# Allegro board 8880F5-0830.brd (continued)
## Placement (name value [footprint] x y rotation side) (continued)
NOREF#872  -  []  119.95 195.15 0 top
NOREF#873  -  []  320.83 194.63 0 top
NOREF#874  -  []  392.24 199.18 90 top
NOREF#875  -  []  215.96 248.49 0 top
NOREF#876  -  []  406.19 188.15 0 top
NOREF#877  -  []  392.47 288.57 90 top
NOREF#878  -  []  262.04 224.74 0 top
NOREF#879  -  []  374.88 217.11 0 top
NOREF#880  -  []  329.16 296.86 0 top
NOREF#881  -  []  406.94 131.34 90 top
NOREF#882  -  []  465.81 179.15 0 top
NOREF#883  -  []  400.79 154.88 0 top
NOREF#884  -  []  390.53 171.64 0 top
NOREF#885  -  []  223.15 211.32 90 top
NOREF#886  -  []  417.7 154.88 0 top
NOREF#887  -  []  387.08 154.88 0 top
NOREF#888  -  []  419.9 240.56 90 top
NOREF#889  -  []  201.66 213.45 90 top
NOREF#890  -  []  352.24 243.59 90 top
NOREF#891  -  []  406.95 131.44 90 top
NOREF#892  -  []  272.55 243.91 0 top
NOREF#893  -  []  381.2 226.12 90 top
NOREF#894  -  []  409.49 180.15 0 top
NOREF#895  -  []  200.98 260.9 90 top
NOREF#896  -  []  272.66 288.86 90 top
NOREF#897  -  []  201.23 233.47 90 top
NOREF#898  -  []  168.13 172.56 90 top
NOREF#899  -  []  251.06 225.04 90 top
NOREF#900  -  []  419.73 131.89 90 top
NOREF#901  -  []  467.51 186.77 0 top
NOREF#902  -  []  460.93 191.31 90 top
NOREF#903  -  []  192.47 205.19 90 top
NOREF#904  -  []  419.9 272.82 90 top
NOREF#905  -  []  409.17 249.11 0 top
NOREF#906  -  []  184.47 241.43 0 top
NOREF#907  -  []  303.47 154.05 0 top
NOREF#908  -  []  340.61 286.96 90 top
NOREF#909  -  []  175.7 177.76 90 top
NOREF#910  -  []  272.55 245.18 0 top
NOREF#911  -  []  216.96 240.71 0 top
NOREF#912  -  []  295.96 248.49 0 top
NOREF#913  -  []  418.63 131.94 90 top
NOREF#914  -  []  115.61 211.51 90 top
NOREF#915  -  []  199.33 240.28 90 top
NOREF#916  -  []  117.26 190.55 90 top
NOREF#917  -  []  252.51 265.56 0 top
NOREF#918  -  []  327.27 131.64 90 top
NOREF#919  -  []  192.47 177.76 90 top
NOREF#920  -  []  122.15 195.15 0 top
NOREF#921  -  []  311.44 288.86 0 top
NOREF#922  -  []  351.34 183.91 0 top
NOREF#923  -  []  317.57 269.63 90 top
NOREF#924  -  []  390.94 224.9 90 top
NOREF#925  -  []  209.23 236.67 90 top
NOREF#926  -  []  398.65 289.12 0 top
NOREF#927  -  []  331.06 163.82 90 top
NOREF#928  -  []  108.01 195.15 0 top
NOREF#929  -  []  369.38 241.11 0 top
NOREF#930  -  []  351.04 241.69 0 top
NOREF#931  -  []  177.33 228.47 90 top
NOREF#932  -  []  352.55 182.64 0 top
NOREF#933  -  []  310.43 243.09 0 top
NOREF#934  -  []  230.73 193.69 0 top
NOREF#935  -  []  122.15 222.33 0 top
NOREF#936  -  []  194.09 228.47 90 top
NOREF#937  -  []  251.54 252.73 90 top
NOREF#938  -  []  306.27 216.63 90 top
NOREF#939  -  []  343.31 224.74 0 top
NOREF#940  -  []  451.68 171.53 0 top
NOREF#941  -  []  258.2 186.67 0 top
NOREF#942  -  []  175.7 209.49 90 top
NOREF#943  -  []  377.23 257.16 90 top
NOREF#944  -  []  392.47 272.56 90 top
NOREF#945  -  []  298.16 237.06 0 top
NOREF#946  -  []  262.04 164.74 0 top
NOREF#947  -  []  346.08 288.86 0 top
NOREF#948  -  []  287.91 280.1 0 top
NOREF#949  -  []  110.47 178.64 0 top
NOREF#950  -  []  201.49 151.93 90 top
NOREF#951  -  []  271.34 245.18 0 top
NOREF#952  -  []  354.37 130.67 90 top
NOREF#953  -  []  313.94 286.96 90 top
NOREF#954  -  []  175.8 133.97 90 top
NOREF#955  -  []  304.82 146.05 0 top
NOREF#956  -  []  332.51 265.55 0 top
NOREF#957  -  []  166.06 175.58 90 top
NOREF#958  -  []  309.51 183.41 0 top
NOREF#959  -  []  343.83 231.63 90 top
NOREF#960  -  []  184.47 201.89 90 top
NOREF#961  -  []  230.73 253.69 0 top
NOREF#962  -  []  406.65 271.21 90 top
NOREF#963  -  []  477.24 239.09 0 top
NOREF#964  -  []  331.94 264.65 90 top
NOREF#965  -  []  342.04 224.72 0 top
NOREF#966  -  []  306.92 146.05 0 top
NOREF#967  -  []  115.99 130.36 90 top
NOREF#968  -  []  401.52 210.88 90 top
NOREF#969  -  []  385.61 208.66 90 top
NOREF#970  -  []  383.07 180.2 90 top
NOREF#971  -  []  257.09 224.74 90 top
NOREF#972  -  []  327.57 205.86 90 top
NOREF#973  -  []  303.15 271.32 90 top
NOREF#974  -  []  168.69 290.01 90 top
NOREF#975  -  []  106.36 190.55 0 top
NOREF#976  -  []  465.81 222.58 0 top
NOREF#977  -  []  337.09 223.52 90 top
NOREF#978  -  []  331.62 204.35 90 top
NOREF#979  -  []  456.08 230.2 0 top
NOREF#980  -  []  310.43 183.09 0 top
NOREF#981  -  []  261.63 233.83 90 top
NOREF#982  -  []  339.33 204.35 90 top
NOREF#983  -  []  175.8 174.36 90 top
NOREF#984  -  []  247.89 264.35 90 top
NOREF#985  -  []  263.71 288.86 0 top
NOREF#986  -  []  383.07 163.44 90 top
NOREF#987  -  []  387.39 281.11 0 top
NOREF#988  -  []  201.66 240.88 90 top
NOREF#989  -  []  418.37 273.42 90 top
NOREF#990  -  []  175.8 256.4 90 top
NOREF#991  -  []  451.68 214.96 0 top
NOREF#992  -  []  352.24 184.86 90 top
NOREF#993  -  []  342.36 225.04 90 top
NOREF#994  -  []  394.66 274.38 90 top
NOREF#995  -  []  346.27 132.97 90 top
NOREF#996  -  []  251.54 192.73 90 top
NOREF#997  -  []  317.05 288.86 0 top
NOREF#998  -  []  201.66 186.02 90 top
NOREF#999  -  []  346.27 129.42 90 top
NOREF#1000  -  []  380.59 287.22 0 top
NOREF#1001  -  []  266.49 143.19 0 top
NOREF#1002  -  []  118.96 179.19 0 top
NOREF#1003  -  []  306.85 271.67 0 top
NOREF#1004  -  []  199.33 185.42 90 top
NOREF#1005  -  []  319.33 176.03 90 top
NOREF#1006  -  []  234.7 298.51 0 top
NOREF#1007  -  []  167.7 132.72 90 top
NOREF#1008  -  []  456.08 186.77 0 top
NOREF#1009  -  []  371.48 257.11 0 top
NOREF#1010  -  []  110.21 222.33 0 top
NOREF#1011  -  []  230.43 248.88 0 top
NOREF#1012  -  []  167.7 192.32 90 top
NOREF#1013  -  []  404.15 289.12 0 top
NOREF#1014  -  []  423.61 188.92 90 top
NOREF#1015  -  []  392.04 241.11 90 top
NOREF#1016  -  []  167.7 242.78 90 top
NOREF#1017  -  []  273.09 288.41 90 top
NOREF#1018  -  []  165.8 171.96 90 top
NOREF#1019  -  []  310.43 188.88 90 top
NOREF#1020  -  []  397.8 179.7 90 top
NOREF#1021  -  []  259.33 205.55 0 top
NOREF#1022  -  []  330.49 224.74 90 top
NOREF#1023  -  []  425.2 161.74 90 top
NOREF#1024  -  []  229.21 247.61 0 top
NOREF#1025  -  []  481.96 273.87 90 top
NOREF#1026  -  []  249.6 163.52 90 top
NOREF#1027  -  []  229.51 253.69 0 top
NOREF#1028  -  []  392.73 188.15 0 top
NOREF#1029  -  []  239.33 183.63 90 top
NOREF#1030  -  []  473.79 239.64 0 top
NOREF#1031  -  []  462.06 274.77 90 top
NOREF#1032  -  []  336.45 164.74 0 top
NOREF#1033  -  []  184.47 214 0 top
NOREF#1034  -  []  463.11 186.77 0 top
NOREF#1035  -  []  396.55 257.37 0 top
NOREF#1036  -  []  257.9 186.99 0 top
NOREF#1037  -  []  127.81 175.44 90 top
NOREF#1038  -  []  230.73 249.2 0 top
NOREF#1039  -  []  201.21 276.04 90 top
NOREF#1040  -  []  331.38 163.52 90 top
NOREF#1041  -  []  475.04 195.66 0 top
NOREF#1042  -  []  478.57 259.9 90 top
NOREF#1043  -  []  251.62 205.56 90 top
NOREF#1044  -  []  284.77 146.93 90 top
NOREF#1045  -  []  184.47 192.32 90 top
NOREF#1046  -  []  229.51 246.66 0 top
NOREF#1047  -  []  309.51 246.66 0 top
NOREF#1048  -  []  119.95 187.53 0 top
NOREF#1049  -  []  392.24 193.43 90 top
NOREF#1050  -  []  334.29 204.35 90 top
NOREF#1051  -  []  332.51 204.35 90 top
NOREF#1052  -  []  252.83 265.86 90 top
NOREF#1053  -  []  386.53 148.15 90 top
NOREF#1054  -  []  415.6 146.88 0 top
NOREF#1055  -  []  124.1 231.22 0 top
NOREF#1056  -  []  413.75 171.64 0 top
NOREF#1057  -  []  329.28 165.04 90 top
NOREF#1058  -  []  424.05 163.64 90 top
NOREF#1059  -  []  371.73 289.12 0 top
NOREF#1060  -  []  475.04 195.66 0 top
NOREF#1061  -  []  120.24 171.1 0 top
NOREF#1062  -  []  383.09 273.11 0 top
NOREF#1063  -  []  295.19 271.65 90 top
NOREF#1064  -  []  331.62 205.56 0 top
NOREF#1065  -  []  108.01 214.71 0 top
NOREF#1066  -  []  310.83 224.63 0 top
NOREF#1067  -  []  184.47 165.4 90 top
NOREF#1068  -  []  419.47 273.37 90 top
NOREF#1069  -  []  396.55 257.37 0 top
NOREF#1070  -  []  334.61 205.86 90 top
NOREF#1071  -  []  384.17 180.15 90 top
NOREF#1072  -  []  309.21 183.09 0 top
NOREF#1073  -  []  118.7 222.88 0 top
NOREF#1074  -  []  340.83 174.63 90 top
NOREF#1075  -  []  388.43 146.88 0 top
NOREF#1076  -  []  450.03 234.74 0 top
NOREF#1077  -  []  398.65 209.36 90 top
NOREF#1078  -  []  166.06 189.04 90 top
NOREF#1079  -  []  258.35 288.91 90 top
NOREF#1080  -  []  217.41 213.24 90 top
NOREF#1081  -  []  230.43 187.61 0 top
NOREF#1082  -  []  341.63 173.83 90 top
NOREF#1083  -  []  390.53 180.15 0 top
NOREF#1084  -  []  373.87 188.15 0 top
NOREF#1085  -  []  395.2 297.12 0 top
NOREF#1086  -  []  310.41 187.61 90 top
NOREF#1087  -  []  330.17 225.04 90 top
NOREF#1088  -  []  223.56 245.29 90 top
NOREF#1089  -  []  272.25 181.05 90 top
NOREF#1090  -  []  396.55 273.11 0 top
NOREF#1091  -  []  473.79 196.21 0 top
NOREF#1092  -  []  326.23 173.13 0 top
NOREF#1093  -  []  400.24 195.88 90 top
NOREF#1094  -  []  327.57 204.65 90 top
NOREF#1095  -  []  35.83 128.17 90 top
NOREF#1096  -  []  124.61 178.64 0 top
NOREF#1097  -  []  184.47 204.09 90 top
NOREF#1098  -  []  201.49 161 90 top
NOREF#1099  -  []  408.63 290.39 90 top
NOREF#1100  -  []  184.47 260.9 90 top
NOREF#1101  -  []  318.45 197.01 0 top
NOREF#1102  -  []  461.86 230.75 0 top
NOREF#1103  -  []  184.47 149.48 90 top
NOREF#1104  -  []  167.7 233.47 90 top
NOREF#1105  -  []  400.85 297.12 0 top
NOREF#1106  -  []  175.7 246.08 90 top
NOREF#1107  -  []  115.36 235.64 90 top
NOREF#1108  -  []  381.2 290.39 90 top
NOREF#1109  -  []  456.04 179.06 0 top
NOREF#1110  -  []  165.8 212.85 90 top
NOREF#1111  -  []  201.23 247.18 90 top
NOREF#1112  -  []  167.7 255.15 0 top
NOREF#1113  -  []  528.1 276.41 90 top
NOREF#1114  -  []  409.74 146.88 0 top
NOREF#1115  -  []  273.09 288.31 90 top
NOREF#1116  -  []  251.05 264.65 90 top
NOREF#1117  -  []  317.98 163.82 90 top
NOREF#1118  -  []  199.84 162.12 90 top
NOREF#1119  -  []  184.89 254.6 90 top
NOREF#1120  -  []  295.96 177.06 0 top
NOREF#1121  -  []  182.57 212.85 0 top
NOREF#1122  -  []  184.47 241.43 90 top
NOREF#1123  -  []  479.44 195.66 0 top
NOREF#1124  -  []  468.01 222.58 0 top
NOREF#1125  -  []  167.7 227.72 90 top
NOREF#1126  -  []  330.51 288.86 0 top
NOREF#1127  -  []  384.17 163.39 90 top
NOREF#1128  -  []  459.28 192.71 90 top
NOREF#1129  -  []  352.25 184.23 0 top
NOREF#1130  -  []  371.73 281.11 0 top
NOREF#1131  -  []  424.98 146.43 90 top
NOREF#1132  -  []  373.73 207.21 0 top
NOREF#1133  -  []  471.21 219.38 90 top
NOREF#1134  -  []  272.24 184.86 90 top
NOREF#1135  -  []  331.54 252.73 90 top
NOREF#1136  -  []  262.68 223.52 90 top
NOREF#1137  -  []  409.43 139.89 0 top
NOREF#1138  -  []  281.47 296.86 0 top
NOREF#1139  -  []  403.99 188.15 0 top
NOREF#1140  -  []  270.04 280.1 0 top
NOREF#1141  -  []  461.96 174.55 0 top
NOREF#1142  -  []  241.6 296.61 0 top
NOREF#1143  -  []  253.72 204.65 90 top
NOREF#1144  -  []  175.7 164.3 90 top
NOREF#1145  -  []  396.55 225.11 0 top
NOREF#1146  -  []  412.79 209.16 90 top
NOREF#1147  -  []  420.37 255.47 90 top
NOREF#1148  -  []  413.51 207.71 90 top
NOREF#1149  -  []  388.43 146.88 0 top
NOREF#1150  -  []  295.96 188.49 0 top
NOREF#1151  -  []  383.09 241.11 0 top
NOREF#1152  -  []  396.28 146.93 90 top
NOREF#1153  -  []  332.83 204.65 90 top
NOREF#1154  -  []  239.33 243.63 90 top
NOREF#1155  -  []  230.73 249.2 0 top
NOREF#1156  -  []  250.18 242.88 0 top
NOREF#1157  -  []  317.98 165.04 90 top
NOREF#1158  -  []  251.94 205.86 90 top
NOREF#1159  -  []  333.4 205.55 0 top
NOREF#1160  -  []  396.22 139.89 0 top
NOREF#1161  -  []  460.93 166.93 90 top
NOREF#1162  -  []  495.08 259.9 90 top
NOREF#1163  -  []  259.33 265.55 0 top
NOREF#1164  -  []  303.56 173.86 90 top
NOREF#1165  -  []  121.9 231.22 0 top
NOREF#1166  -  []  384.36 131.89 0 top
NOREF#1167  -  []  339.65 264.65 90 top
NOREF#1168  -  []  334.29 265.55 0 top
NOREF#1169  -  []  389.7 209.36 0 top
NOREF#1170  -  []  383.09 257.11 0 top
NOREF#1171  -  []  272.8 157.28 0 top
NOREF#1172  -  []  199.33 212.85 0 top
NOREF#1173  -  []  311.69 288.91 90 top
NOREF#1174  -  []  463.61 171.53 0 top
NOREF#1175  -  []  463.11 230.2 0 top
NOREF#1176  -  []  331.86 252.43 90 top
NOREF#1177  -  []  415.61 185.72 90 top
NOREF#1178  -  []  106.76 215.26 0 top
NOREF#1179  -  []  217.71 216.09 0 top
NOREF#1180  -  []  415.61 185.72 90 top
NOREF#1181  -  []  394.05 271.21 0 top
NOREF#1182  -  []  250.17 225.04 90 top
NOREF#1183  -  []  417.2 171.64 0 top
NOREF#1184  -  []  167.7 255.15 90 top
NOREF#1185  -  []  475.36 127 90 top
NOREF#1186  -  []  375.22 180.15 0 top
NOREF#1187  -  []  392.47 224.3 90 top
NOREF#1188  -  []  165.8 144.78 0 top
NOREF#1189  -  []  459.24 175.86 0 top
NOREF#1190  -  []  338.2 186.67 0 top
NOREF#1191  -  []  405.42 131.94 90 top
NOREF#1192  -  []  336.77 223.82 90 top
NOREF#1193  -  []  237.83 257.63 0 top
NOREF#1194  -  []  209.49 182.06 90 top
NOREF#1195  -  []  229.51 183.41 0 top
NOREF#1196  -  []  192.47 182.06 90 top
NOREF#1197  -  []  385.18 209.11 90 top
NOREF#1198  -  []  408.02 287.22 0 top
NOREF#1199  -  []  292.74 296.86 0 top
NOREF#1200  -  []  247.25 264.35 90 top
NOREF#1201  -  []  301.56 239.06 0 top
NOREF#1202  -  []  107.02 171.57 0 top
NOREF#1203  -  []  329.85 164.74 0 top
NOREF#1204  -  []  259.65 204.65 90 top
NOREF#1205  -  []  330.74 224.72 0 top
NOREF#1206  -  []  400.85 265.37 0 top
NOREF#1207  -  []  305.83 204.31 0 top
NOREF#1208  -  []  483.04 195.66 0 top
NOREF#1209  -  []  371.73 273.11 0 top
NOREF#1210  -  []  383.09 257.11 0 top
NOREF#1211  -  []  333.72 205.86 90 top
NOREF#1212  -  []  122.19 214.79 0 top
NOREF#1213  -  []  330.49 164.74 90 top
NOREF#1214  -  []  341.48 286.96 0 top
NOREF#1215  -  []  332.51 265.56 0 top
NOREF#1216  -  []  310.41 183.09 90 top
NOREF#1217  -  []  201.21 292.55 90 top
NOREF#1218  -  []  127.7 231.22 0 top
NOREF#1219  -  []  167.7 200.54 0 top
NOREF#1220  -  []  400.24 198.08 90 top
NOREF#1221  -  []  304.61 131.64 0 top
NOREF#1222  -  []  167.7 214 0 top
NOREF#1223  -  []  333.72 265.86 90 top
NOREF#1224  -  []  331.06 165.04 90 top
NOREF#1225  -  []  273.95 147.38 90 top
NOREF#1226  -  []  518.38 292.92 90 top
NOREF#1227  -  []  394.46 129.99 90 top
NOREF#1228  -  []  292.74 288.86 0 top
NOREF#1229  -  []  322.23 233.13 0 top
NOREF#1230  -  []  410.78 131.89 0 top
NOREF#1231  -  []  511.59 273.87 90 top
NOREF#1232  -  []  317.98 225.04 90 top
NOREF#1233  -  []  251.38 223.52 90 top
NOREF#1234  -  []  293.66 272.15 90 top
NOREF#1235  -  []  244.8 288.61 0 top
NOREF#1236  -  []  377.32 163.39 0 top
NOREF#1237  -  []  184.89 240.88 90 top
NOREF#1238  -  []  251.05 205.86 90 top
NOREF#1239  -  []  182.82 243.9 90 top
NOREF#1240  -  []  239.33 176.03 90 top
NOREF#1241  -  []  167.7 241.43 0 top
NOREF#1242  -  []  552.76 299.72 0 top
NOREF#1243  -  []  393.19 239.21 90 top
NOREF#1244  -  []  112.67 178.64 0 top
NOREF#1245  -  []  352.24 183.59 90 top
NOREF#1246  -  []  167.7 178.86 90 top
NOREF#1247  -  []  182.57 254 0 top
NOREF#1248  -  []  184.89 186.02 90 top
NOREF#1249  -  []  450.03 182.17 0 top
NOREF#1250  -  []  259.88 288.31 90 top
NOREF#1251  -  []  167.7 204.09 90 top
NOREF#1252  -  []  248.33 247.93 0 top
NOREF#1253  -  []  410.78 131.89 0 top
NOREF#1254  -  []  309.51 247.93 0 top
NOREF#1255  -  []  230.73 183.41 0 top
NOREF#1256  -  []  554.86 298.45 0 top
NOREF#1257  -  []  218.13 214.06 90 top
NOREF#1258  -  []  386.33 207.21 90 top
NOREF#1259  -  []  460.89 174.46 90 top
NOREF#1260  -  []  250.5 288.86 0 top
NOREF#1261  -  []  107.02 166.42 90 top
NOREF#1262  -  []  107.18 246.83 90 top
NOREF#1263  -  []  253.4 265.56 0 top
NOREF#1264  -  []  451.68 230.2 0 top
NOREF#1265  -  []  339.33 265.55 0 top
NOREF#1266  -  []  402.14 146.88 0 top
NOREF#1267  -  []  312.25 211.67 90 top
NOREF#1268  -  []  459.28 211.76 90 top
NOREF#1269  -  []  263.83 171.63 90 top
NOREF#1270  -  []  310.43 193.37 90 top
NOREF#1271  -  []  75.98 287.84 90 top
NOREF#1272  -  []  343.31 164.72 0 top
NOREF#1273  -  []  402.14 146.88 0 top
NOREF#1274  -  []  230.43 183.09 0 top
NOREF#1275  -  []  384.59 179.7 90 top
NOREF#1276  -  []  290.64 288.86 0 top
NOREF#1277  -  []  401.89 163.64 0 top
NOREF#1278  -  []  483.17 130.26 90 top
NOREF#1279  -  []  330.17 165.04 90 top
NOREF#1280  -  []  306.85 211.67 0 top
NOREF#1281  -  []  118.7 188.08 0 top
NOREF#1282  -  []  239.4 296.61 0 top
NOREF#1283  -  []  400.91 207.71 0 top
NOREF#1284  -  []  399.99 181.42 90 top
NOREF#1285  -  []  75.98 290.38 90 top
NOREF#1286  -  []  124.35 195.15 0 top
NOREF#1287  -  []  83.77 247.51 90 top
NOREF#1288  -  []  410.27 257.37 0 top
NOREF#1289  -  []  302.92 147.32 90 top
NOREF#1290  -  []  270.04 135.24 90 top
NOREF#1291  -  []  412.62 289.12 0 top
NOREF#1292  -  []  108.27 178.64 0 top
NOREF#1293  -  []  261.63 195.43 90 top
NOREF#1294  -  []  318.3 224.74 90 top
NOREF#1295  -  []  184.47 190.12 90 top
NOREF#1296  -  []  250.73 264.35 90 top
NOREF#1297  -  []  410.52 273.37 0 top
NOREF#1298  -  []  317.83 197.63 0 top
NOREF#1299  -  []  332.83 264.65 90 top
NOREF#1300  -  []  478.57 293.82 90 top
NOREF#1301  -  []  256.45 164.72 0 top
NOREF#1302  -  []  351.04 245.5 0 top
NOREF#1303  -  []  288.74 290.13 90 top
NOREF#1304  -  []  405.93 256.92 90 top
NOREF#1305  -  []  410.52 241.11 0 top
NOREF#1306  -  []  337.9 246.99 0 top
NOREF#1307  -  []  259.65 205.86 90 top
NOREF#1308  -  []  192.47 250.38 90 top
NOREF#1309  -  []  369.38 257.11 0 top
NOREF#1310  -  []  217.83 234.63 90 top
NOREF#1311  -  []  310.41 186.34 90 top
NOREF#1312  -  []  309.51 243.41 0 top
NOREF#1313  -  []  329.28 225.04 90 top
NOREF#1314  -  []  201.23 244.98 90 top
NOREF#1315  -  []  259.33 265.55 0 top
NOREF#1316  -  []  317.66 164.74 0 top
NOREF#1317  -  []  309.21 188.88 0 top
NOREF#1318  -  []  422.7 163.64 0 top
NOREF#1319  -  []  369.38 224.6 0 top
NOREF#1320  -  []  352.25 182.32 90 top
NOREF#1321  -  []  254.29 205.56 90 top
NOREF#1322  -  []  201.49 176.66 90 top
NOREF#1323  -  []  262.36 163.82 90 top
NOREF#1324  -  []  184.47 233.47 90 top
NOREF#1325  -  []  228.36 262.16 45 top
NOREF#1326  -  []  462.06 291.28 90 top
NOREF#1327  -  []  286.55 288.41 90 top
NOREF#1328  -  []  411.26 179.7 90 top
NOREF#1329  -  []  369.38 257.11 0 top
NOREF#1330  -  []  175.8 228.97 90 top
NOREF#1331  -  []  185.2 292.55 90 top
NOREF#1332  -  []  247.57 204.65 90 top
NOREF#1333  -  []  343.63 223.82 90 top
NOREF#1334  -  []  342.63 296.86 0 top
NOREF#1335  -  []  199.59 216.47 90 top
NOREF#1336  -  []  397.3 209.36 0 top
NOREF#1337  -  []  66.26 287.84 90 top
NOREF#1338  -  []  110.47 171.02 0 top
NOREF#1339  -  []  327.15 286.96 90 top
NOREF#1340  -  []  352.25 185.5 0 top
NOREF#1341  -  []  328.42 129.74 90 top
NOREF#1342  -  []  118.96 179.19 0 top
NOREF#1343  -  []  473.79 191.06 90 top
NOREF#1344  -  []  175.7 195.52 90 top
NOREF#1345  -  []  369.63 289.12 0 top
NOREF#1346  -  []  390.59 195.9 90 top
NOREF#1347  -  []  381.74 232.85 0 top
NOREF#1348  -  []  175.8 201.79 90 top
NOREF#1349  -  []  257.09 163.52 90 top
NOREF#1350  -  []  461.86 182.17 90 top
NOREF#1351  -  []  294.94 296.86 0 top
NOREF#1352  -  []  122.15 187.53 0 top
NOREF#1353  -  []  201.23 214 90 top
NOREF#1354  -  []  394.05 255.47 0 top
NOREF#1355  -  []  167.7 178.86 90 top
NOREF#1356  -  []  220.36 188.49 0 top
NOREF#1357  -  []  251.62 204.35 90 top
NOREF#1358  -  []  272.55 185.18 0 top
NOREF#1359  -  []  406.65 239.21 90 top
NOREF#1360  -  []  511.59 291.28 90 top
NOREF#1361  -  []  309.12 154.05 0 top
NOREF#1362  -  []  209.23 250.38 90 top
NOREF#1363  -  []  167.7 215.35 90 top
NOREF#1364  -  []  201.23 217.55 90 top
NOREF#1365  -  []  396.03 180.15 0 top
NOREF#1366  -  []  463.61 222.58 0 top
NOREF#1367  -  []  216.96 252.14 0 top
NOREF#1368  -  []  228.36 202.16 45 top
NOREF#1369  -  []  272.24 189.18 90 top
NOREF#1370  -  []  229.21 193.37 0 top
NOREF#1371  -  []  230.43 183.09 90 top
NOREF#1372  -  []  327.25 204.35 90 top
NOREF#1373  -  []  396.55 289.12 0 top
NOREF#1374  -  []  463.11 230.2 0 top
NOREF#1375  -  []  220.36 177.06 0 top
NOREF#1376  -  []  201.21 290.01 90 top
NOREF#1377  -  []  270.04 280.1 0 top
NOREF#1378  -  []  271.04 244.23 0 top
NOREF#1379  -  []  423.61 182.42 90 top
NOREF#1380  -  []  273.5 148.65 90 top
NOREF#1381  -  []  528.1 273.87 90 top
NOREF#1382  -  []  305.94 296.86 0 top
NOREF#1383  -  []  405.17 131.89 0 top
NOREF#1384  -  []  419.22 257.37 90 top
NOREF#1385  -  []  175.7 154.88 90 top
NOREF#1386  -  []  318.3 164.74 90 top
NOREF#1387  -  []  309.05 211.67 0 top
NOREF#1388  -  []  398.65 249.11 0 top
NOREF#1389  -  []  397.55 209.41 90 top
NOREF#1390  -  []  385.93 144.98 0 top
NOREF#1391  -  []  339.33 265.56 0 top
NOREF#1392  -  []  351.04 189.18 0 top
NOREF#1393  -  []  352.24 182.32 90 top
NOREF#1394  -  []  409.17 297.12 0 top
NOREF#1395  -  []  256.77 163.82 90 top
NOREF#1396  -  []  119.95 187.53 0 top
NOREF#1397  -  []  451.68 195.91 0 top
NOREF#1398  -  []  192.47 189.02 90 top
NOREF#1399  -  []  451.68 230.2 0 top
NOREF#1400  -  []  313.98 131.19 90 top
NOREF#1401  -  []  352.55 181.37 0 top
NOREF#1402  -  []  118.74 215.34 0 top
NOREF#1403  -  []  390.34 192.28 90 top
NOREF#1404  -  []  175.7 189.02 90 top
NOREF#1405  -  []  327.57 265.86 90 top
NOREF#1406  -  []  388.43 163.64 0 top
NOREF#1407  -  []  107.02 174.04 90 top
NOREF#1408  -  []  383.09 224.85 0 top
NOREF#1409  -  []  453.88 230.2 0 top
NOREF#1410  -  []  200.98 255.15 90 top
NOREF#1411  -  []  352.25 181.05 90 top
NOREF#1412  -  []  518.38 290.38 90 top
NOREF#1413  -  []  252.51 205.56 90 top
NOREF#1414  -  []  208.98 259.8 90 top
NOREF#1415  -  []  369.63 273.11 0 top
NOREF#1416  -  []  354.27 134.07 90 top
NOREF#1417  -  []  352.24 181.05 90 top
NOREF#1418  -  []  219.81 273.69 90 top
NOREF#1419  -  []  106.76 215.26 0 top
NOREF#1420  -  []  383.73 195.88 90 top
NOREF#1421  -  []  218.16 188.49 0 top
NOREF#1422  -  []  155.57 289.11 90 top
NOREF#1423  -  []  249.85 224.72 0 top
NOREF#1424  -  []  401.89 163.64 0 top
NOREF#1425  -  []  317.66 224.74 0 top
NOREF#1426  -  []  351.34 189.5 0 top
NOREF#1427  -  []  352.25 182.96 0 top
NOREF#1428  -  []  468.01 171.53 0 top
NOREF#1429  -  []  263.85 273.37 90 top
NOREF#1430  -  []  329.6 164.74 90 top
NOREF#1431  -  []  309.21 193.37 0 top
NOREF#1432  -  []  263.95 223.52 90 top
NOREF#1433  -  []  263.14 270.2 90 top
NOREF#1434  -  []  403.41 209.61 0 top
NOREF#1435  -  []  379 288.57 90 top
NOREF#1436  -  []  167.7 173.11 0 top
NOREF#1437  -  []  408.37 258.64 90 top
NOREF#1438  -  []  250.73 205.55 0 top
NOREF#1439  -  []  93.76 271.33 90 top
NOREF#1440  -  []  310.43 189.52 0 top
NOREF#1441  -  []  251.06 223.82 90 top
NOREF#1442  -  []  226.27 216.63 90 top
NOREF#1443  -  []  397.38 163.64 90 top
NOREF#1444  -  []  225.83 264.31 0 top
NOREF#1445  -  []  263.63 163.82 90 top
NOREF#1446  -  []  118.74 210.19 90 top
NOREF#1447  -  []  119.95 195.15 0 top
NOREF#1448  -  []  217.41 273.24 90 top
NOREF#1449  -  []  175.7 141.67 90 top
NOREF#1450  -  []  175.7 135.17 90 top
NOREF#1451  -  []  234.33 228.13 90 top
NOREF#1452  -  []  218.16 237.06 0 top
NOREF#1453  -  []  448.94 276.41 90 top
NOREF#1454  -  []  192.57 201.79 90 top
NOREF#1455  -  []  310.43 194.01 0 top
NOREF#1456  -  []  377.48 289.17 90 top
NOREF#1457  -  []  400.54 188.15 0 top
NOREF#1458  -  []  397.38 146.88 90 top
NOREF#1459  -  []  272.55 242.64 0 top
NOREF#1460  -  []  283.21 282 0 top
NOREF#1461  -  []  485.36 289.48 90 top
NOREF#1462  -  []  351.04 181.69 0 top
NOREF#1463  -  []  250.5 288.86 0 top
NOREF#1464  -  []  424.98 146.33 90 top
NOREF#1465  -  []  108.01 222.33 0 top
NOREF#1466  -  []  248.21 132.69 90 top
NOREF#1467  -  []  127.55 184.33 90 top
NOREF#1468  -  []  411.99 161.74 90 top
NOREF#1469  -  []  419.9 288.67 90 top
NOREF#1470  -  []  128.05 273.87 90 top
NOREF#1471  -  []  253.4 205.56 0 top
NOREF#1472  -  []  304.82 146.05 0 top
NOREF#1473  -  []  36.1 129.71 90 top
NOREF#1474  -  []  258.2 246.67 0 top
NOREF#1475  -  []  107.02 179.19 0 top
NOREF#1476  -  []  101.82 290.38 90 top
NOREF#1477  -  []  387.2 207.46 0 top
NOREF#1478  -  []  405.5 225.11 90 top
NOREF#1479  -  []  402.06 217.61 0 top
NOREF#1480  -  []  389.7 209.36 0 top
NOREF#1481  -  []  330.18 242.88 0 top
NOREF#1482  -  []  388.43 180.15 0 top
NOREF#1483  -  []  250.74 164.72 0 top
NOREF#1484  -  []  184.47 174.46 90 top
NOREF#1485  -  []  379.52 188.15 0 top
NOREF#1486  -  []  238.3 164.74 90 top
NOREF#1487  -  []  377.23 224.65 90 top
NOREF#1488  -  []  546.67 300.44 90 top
NOREF#1489  -  []  369.38 241.11 0 top
NOREF#1490  -  []  199.59 158.5 90 top
NOREF#1491  -  []  461.86 230.75 0 top
NOREF#1492  -  []  105.93 204.27 90 top
NOREF#1493  -  []  184.47 163.2 90 top
NOREF#1494  -  []  106.18 160.58 90 top
NOREF#1495  -  []  387.39 265.11 0 top
NOREF#1496  -  []  425.23 180.72 90 top
NOREF#1497  -  []  184.47 242.78 90 top
NOREF#1498  -  []  398.53 144.98 90 top
NOREF#1499  -  []  272.55 181.37 0 top
NOREF#1500  -  []  511.59 257.36 90 top
NOREF#1501  -  []  328.33 247.93 0 top
NOREF#1502  -  []  414.82 281.37 0 top
NOREF#1503  -  []  172.08 272.6 90 top
NOREF#1504  -  []  263.2 172.26 90 top
NOREF#1505  -  []  247.25 204.35 90 top
NOREF#1506  -  []  423.61 184.62 90 top
NOREF#1507  -  []  175.7 137.37 90 top
NOREF#1508  -  []  351.34 182.64 0 top
NOREF#1509  -  []  390.69 273.11 0 top
NOREF#1510  -  []  314.19 145.5 90 top
NOREF#1511  -  []  128.21 178.64 0 top
NOREF#1512  -  []  259.59 133.29 90 top
NOREF#1513  -  []  352.25 245.5 0 top
NOREF#1514  -  []  302.11 240.71 0 top
NOREF#1515  -  []  210.86 201.29 90 top
NOREF#1516  -  []  209.33 228.97 90 top
NOREF#1517  -  []  168.13 254.6 90 top
NOREF#1518  -  []  468.68 129.54 0 top
NOREF#1519  -  []  396.55 257.37 0 top
NOREF#1520  -  []  393.19 271.21 90 top
NOREF#1521  -  []  310.41 193.37 90 top
NOREF#1522  -  []  117.01 234.24 90 top
NOREF#1523  -  []  396.28 180.2 90 top
NOREF#1524  -  []  471.21 211.76 90 top
NOREF#1525  -  []  314.33 228.13 90 top
NOREF#1526  -  []  310.43 254.01 0 top
NOREF#1527  -  []  352.55 245.18 0 top
NOREF#1528  -  []  473.79 196.21 0 top
NOREF#1529  -  []  346.27 129.42 0 top
NOREF#1530  -  []  201.23 187.92 90 top
NOREF#1531  -  []  352.25 244.86 90 top
NOREF#1532  -  []  192.47 162.1 90 top
NOREF#1533  -  []  453.84 222.5 0 top
NOREF#1534  -  []  344.37 128.27 90 top
NOREF#1535  -  []  419.64 256.82 90 top
NOREF#1536  -  []  241.82 167.13 90 top
NOREF#1537  -  []  298.13 274.06 0 top
NOREF#1538  -  []  216.96 192.14 0 top
NOREF#1539  -  []  310.43 247.61 90 top
NOREF#1540  -  []  468.01 179.15 0 top
NOREF#1541  -  []  369.38 224.6 0 top
NOREF#1542  -  []  471.11 230.2 0 top
NOREF#1543  -  []  306.83 269.63 90 top
NOREF#1544  -  []  330.18 182.88 0 top
NOREF#1545  -  []  371.48 241.11 0 top
NOREF#1546  -  []  184.47 173.11 90 top
NOREF#1547  -  []  165.8 131.57 0 top
NOREF#1548  -  []  223.56 233.86 90 top
NOREF#1549  -  []  253.4 265.56 90 top
NOREF#1550  -  []  201.23 206.29 90 top
NOREF#1551  -  []  331.38 224.74 90 top
NOREF#1552  -  []  167.7 136.27 90 top
NOREF#1553  -  []  230.83 224.63 0 top
NOREF#1554  -  []  235.85 288.61 90 top
NOREF#1555  -  []  412.62 281.37 0 top
NOREF#1556  -  []  385.61 208.56 90 top
NOREF#1557  -  []  184.47 178.86 90 top
NOREF#1558  -  []  368.28 297.12 0 top
NOREF#1559  -  []  392.04 224.85 90 top
NOREF#1560  -  []  334.29 205.55 0 top
NOREF#1561  -  []  175.7 236.67 90 top
NOREF#1562  -  []  300.01 288.31 90 top
NOREF#1563  -  []  382.82 180.15 0 top
NOREF#1564  -  []  252.51 265.55 0 top
NOREF#1565  -  []  300.11 273.24 90 top
NOREF#1566  -  []  263.95 163.52 90 top
NOREF#1567  -  []  312.67 146.1 90 top
NOREF#1568  -  []  107.02 179.19 0 top
NOREF#1569  -  []  375.22 163.39 0 top
NOREF#1570  -  []  343.63 165.04 90 top
NOREF#1571  -  []  401.89 180.15 0 top
NOREF#1572  -  []  384.08 209.16 90 top
NOREF#1573  -  []  254.61 264.65 90 top
NOREF#1574  -  []  209.23 209.49 90 top
NOREF#1575  -  []  450.03 225.6 0 top
NOREF#1576  -  []  320.94 211.63 90 top
NOREF#1577  -  []  378.75 224.05 90 top
NOREF#1578  -  []  327.25 265.55 0 top
NOREF#1579  -  []  119.7 231.22 0 top
NOREF#1580  -  []  199.59 171.96 90 top
NOREF#1581  -  []  399.39 178.25 0 top
NOREF#1582  -  []  351.04 182.96 0 top
NOREF#1583  -  []  352.24 241.05 90 top
NOREF#1584  -  []  343.98 288.86 0 top
NOREF#1585  -  []  412.6 161.74 0 top
NOREF#1586  -  []  411.26 179.6 90 top
NOREF#1587  -  []  414.57 265.37 0 top
NOREF#1588  -  []  217.83 174.63 90 top
NOREF#1589  -  []  333.4 205.56 90 top
NOREF#1590  -  []  215.96 237.06 0 top
NOREF#1591  -  []  395.2 249.11 0 top
NOREF#1592  -  []  478.57 291.28 90 top
NOREF#1593  -  []  478.57 274.77 90 top
NOREF#1594  -  []  472.86 166.93 90 top
NOREF#1595  -  []  352.55 243.91 0 top
NOREF#1596  -  []  378.75 240.56 90 top
NOREF#1597  -  []  272.25 241.05 90 top
NOREF#1598  -  []  229.21 253.37 0 top
NOREF#1599  -  []  167.7 260.9 90 top
NOREF#1600  -  []  249.85 224.74 0 top
NOREF#1601  -  []  333.4 265.56 0 top
NOREF#1602  -  []  230.73 253.69 0 top
NOREF#1603  -  []  209.23 191.22 90 top
NOREF#1604  -  []  251.62 265.56 0 top
NOREF#1605  -  []  296.96 240.71 0 top
NOREF#1606  -  []  215.96 188.49 0 top
NOREF#1607  -  []  182.82 203.01 90 top
NOREF#1608  -  []  275.82 296.86 0 top
NOREF#1609  -  []  319.33 243.63 90 top
NOREF#1610  -  []  254.61 265.86 90 top
NOREF#1611  -  []  250.49 163.52 90 top
NOREF#1612  -  []  165.8 185.42 0 top
NOREF#1613  -  []  201.23 241.43 90 top
NOREF#1614  -  []  250.73 205.56 0 top
NOREF#1615  -  []  343.63 225.04 90 top
NOREF#1616  -  []  412.36 209.61 90 top
NOREF#1617  -  []  383.09 241.11 0 top
NOREF#1618  -  []  299.59 288.86 90 top
NOREF#1619  -  []  118.45 226.62 90 top
NOREF#1620  -  []  342.08 290.13 90 top
NOREF#1621  -  []  383.73 198.08 90 top
NOREF#1622  -  []  317.83 257.63 0 top
NOREF#1623  -  []  101.82 287.84 90 top
NOREF#1624  -  []  210.86 228.47 90 top
NOREF#1625  -  []  184.47 173.11 0 top
NOREF#1626  -  []  261.63 173.83 90 top
NOREF#1627  -  []  271.34 182.64 0 top
NOREF#1628  -  []  192.57 215.25 90 top
NOREF#1629  -  []  272.25 242.32 90 top
NOREF#1630  -  []  182.82 189.04 90 top
NOREF#1631  -  []  242.23 233.13 90 top
NOREF#1632  -  []  456.04 222.5 0 top
NOREF#1633  -  []  201.21 273.5 90 top
NOREF#1634  -  []  300.01 288.41 90 top
NOREF#1635  -  []  177.33 201.29 90 top
NOREF#1636  -  []  302.71 132.91 90 top
NOREF#1637  -  []  330.73 205.56 90 top
NOREF#1638  -  []  369.63 289.12 0 top
NOREF#1639  -  []  404.4 241.16 90 top
NOREF#1640  -  []  334.81 296.86 0 top
NOREF#1641  -  []  253.4 205.56 90 top
NOREF#1642  -  []  249.28 163.82 90 top
NOREF#1643  -  []  318.32 131.64 0 top
NOREF#1644  -  []  121.9 238.84 0 top
NOREF#1645  -  []  239.33 236.03 0 top
NOREF#1646  -  []  290.64 288.86 0 top
NOREF#1647  -  []  451.68 171.53 0 top
NOREF#1648  -  []  182.57 144.78 90 top
NOREF#1649  -  []  398.65 281.11 0 top
NOREF#1650  -  []  192.47 243.88 90 top
NOREF#1651  -  []  184.47 247.18 90 top
NOREF#1652  -  []  209.23 189.02 90 top
NOREF#1653  -  []  165.8 199.39 0 top
NOREF#1654  -  []  314.55 286.96 0 top
NOREF#1655  -  []  417.2 163.64 0 top
NOREF#1656  -  []  393.19 222.95 90 top
NOREF#1657  -  []  167.7 145.93 0 top
NOREF#1658  -  []  194.09 173.86 90 top
NOREF#1659  -  []  406.65 255.47 90 top
NOREF#1660  -  []  236.27 289.16 90 top
NOREF#1661  -  []  451.64 179.06 0 top
NOREF#1662  -  []  263.63 225.04 90 top
NOREF#1663  -  []  472.86 217.98 90 top
NOREF#1664  -  []  331.62 205.55 0 top
NOREF#1665  -  []  325.92 131.64 0 top
NOREF#1666  -  []  367.13 287.22 0 top
NOREF#1667  -  []  108.01 222.33 0 top
NOREF#1668  -  []  166.06 216.47 90 top
NOREF#1669  -  []  423.71 181.22 90 top
NOREF#1670  -  []  271.31 288.86 0 top
NOREF#1671  -  []  327.7 131.19 90 top
NOREF#1672  -  []  252.6 288.86 0 top
NOREF#1673  -  []  96.33 238.84 0 top
NOREF#1674  -  []  249.28 225.04 90 top
NOREF#1675  -  []  165.8 240.28 0 top
NOREF#1676  -  []  166.06 230.19 90 top
NOREF#1677  -  []  322.23 173.13 0 top
NOREF#1678  -  []  501.87 276.41 90 top
NOREF#1679  -  []  341.63 255.43 90 top
NOREF#1680  -  []  310.41 248.88 90 top
NOREF#1681  -  []  247.25 205.55 0 top
NOREF#1682  -  []  295.96 237.06 0 top
NOREF#1683  -  []  256.73 132.14 0 top
NOREF#1684  -  []  314.2 145.6 90 top
NOREF#1685  -  []  271.34 243.91 0 top
NOREF#1686  -  []  389.7 209.36 0 top
NOREF#1687  -  []  390.53 154.88 0 top
NOREF#1688  -  []  175.7 191.22 90 top
NOREF#1689  -  []  410.52 289.12 0 top
NOREF#1690  -  []  184.89 172.56 90 top
NOREF#1691  -  []  398.65 257.37 0 top
NOREF#1692  -  []  249.6 223.52 90 top
NOREF#1693  -  []  398.65 273.11 0 top
NOREF#1694  -  []  268.01 296.86 0 top
NOREF#1695  -  []  253.4 204.35 90 top
NOREF#1696  -  []  271.34 181.37 0 top
NOREF#1697  -  []  167.7 159.65 90 top
NOREF#1698  -  []  200.98 255.15 0 top
NOREF#1699  -  []  387.08 188.15 0 top
NOREF#1700  -  []  256.45 224.74 0 top
NOREF#1701  -  []  456.08 214.96 0 top
NOREF#1702  -  []  201.49 159.65 90 top
NOREF#1703  -  []  175.7 259.8 90 top
NOREF#1704  -  []  177.33 133.47 90 top
NOREF#1705  -  []  209.23 246.08 90 top
NOREF#1706  -  []  381.86 129.99 0 top
NOREF#1707  -  []  415.61 179.97 0 top
NOREF#1708  -  []  108.01 195.15 0 top
NOREF#1709  -  []  177.33 255.9 90 top
NOREF#1710  -  []  378.33 241.11 90 top
NOREF#1711  -  []  184.47 231.27 90 top
NOREF#1712  -  []  465.31 186.77 0 top
NOREF#1713  -  []  326.43 288.41 90 top
NOREF#1714  -  []  234.7 286.71 90 top
NOREF#1715  -  []  192.47 191.22 90 top
NOREF#1716  -  []  184.47 186.57 90 top
NOREF#1717  -  []  260.74 135.19 90 top
NOREF#1718  -  []  251.22 193.63 0 top
NOREF#1719  -  []  248.33 187.93 0 top
NOREF#1720  -  []  408.28 129.99 0 top
NOREF#1721  -  []  168.13 186.02 90 top
NOREF#1722  -  []  127.95 222.33 0 top
NOREF#1723  -  []  453.88 214.96 0 top
NOREF#1724  -  []  184.47 151.68 90 top
NOREF#1725  -  []  301.56 190.49 0 top
NOREF#1726  -  []  165.8 226.57 0 top
NOREF#1727  -  []  461.96 217.98 0 top
NOREF#1728  -  []  184.47 145.93 0 top
NOREF#1729  -  []  223.15 271.32 90 top
NOREF#1730  -  []  66.26 273.87 90 top
NOREF#1731  -  []  264.72 272.65 90 top
NOREF#1732  -  []  247.57 205.86 90 top
NOREF#1733  -  []  88.64 247.45 90 top
NOREF#1734  -  []  119.7 238.84 0 top
NOREF#1735  -  []  11.6 261.68 90 top
NOREF#1736  -  []  459.28 236.14 0 top
NOREF#1737  -  []  272.25 181.69 0 top
NOREF#1738  -  []  254.29 264.35 90 top
NOREF#1739  -  []  390.94 241.16 90 top
NOREF#1740  -  []  352.24 242.32 90 top
NOREF#1741  -  []  184.47 219.75 90 top
NOREF#1742  -  []  259.33 265.56 0 top
NOREF#1743  -  []  412.24 144.98 90 top
NOREF#1744  -  []  118.7 217.73 90 top
NOREF#1745  -  []  272.24 189.18 90 top
NOREF#1746  -  []  310.43 183.09 90 top
NOREF#1747  -  []  405.5 289.12 90 top
NOREF#1748  -  []  380.59 271.21 0 top
NOREF#1749  -  []  259.65 265.86 90 top
NOREF#1750  -  []  311.15 219.63 90 top
NOREF#1751  -  []  310.41 188.88 90 top
NOREF#1752  -  []  119.76 127 90 top
NOREF#1753  -  []  375.22 163.39 0 top
NOREF#1754  -  []  408.02 271.47 0 top
NOREF#1755  -  []  460.93 234.74 90 top
NOREF#1756  -  []  339.46 288.86 90 top
NOREF#1757  -  []  559.43 297.18 90 top
NOREF#1758  -  []  272.25 241.69 0 top
NOREF#1759  -  []  249.85 164.74 0 top
NOREF#1760  -  []  424.47 163.09 90 top
NOREF#1761  -  []  277.17 288.86 0 top
NOREF#1762  -  []  155.57 275.14 90 top
NOREF#1763  -  []  230.41 183.09 90 top
NOREF#1764  -  []  463.61 179.15 0 top
NOREF#1765  -  []  272.55 189.5 0 top
NOREF#1766  -  []  127.7 238.84 0 top
NOREF#1767  -  []  459.24 175.86 90 top
NOREF#1768  -  []  248.96 224.74 0 top
NOREF#1769  -  []  483.04 239.09 0 top
NOREF#1770  -  []  404.15 241.11 0 top
NOREF#1771  -  []  230.41 247.61 90 top
NOREF#1772  -  []  175.7 168.6 90 top
NOREF#1773  -  []  399.64 144.98 0 top
NOREF#1774  -  []  375.73 199.18 90 top
NOREF#1775  -  []  384.59 162.84 90 top
NOREF#1776  -  []  230.43 243.09 90 top
NOREF#1777  -  []  310.73 243.41 0 top
NOREF#1778  -  []  249.13 140.14 0 top
NOREF#1779  -  []  230.43 193.37 0 top
NOREF#1780  -  []  351.34 185.18 0 top
NOREF#1781  -  []  410.52 273.37 0 top
NOREF#1782  -  []  352.25 249.82 0 top
NOREF#1783  -  []  283.91 273.37 90 top
NOREF#1784  -  []  112.41 222.33 0 top
NOREF#1785  -  []  222.11 192.14 0 top
NOREF#1786  -  []  410.52 289.12 0 top
NOREF#1787  -  []  326.23 233.13 0 top
NOREF#1788  -  []  116.01 222.33 0 top
NOREF#1789  -  []  36.1 131.91 0 top
NOREF#1790  -  []  384.59 179.6 90 top
NOREF#1791  -  []  327.25 265.55 0 top
NOREF#1792  -  []  298.49 288.91 90 top
NOREF#1793  -  []  381.2 258.38 90 top
NOREF#1794  -  []  168.13 159.1 90 top
NOREF#1795  -  []  330.51 288.86 0 top
NOREF#1796  -  []  279.27 296.86 0 top
NOREF#1797  -  []  116.27 178.64 0 top
NOREF#1798  -  []  231.15 219.63 90 top
NOREF#1799  -  []  297.83 174.63 90 top
NOREF#1800  -  []  328.96 224.74 0 top
NOREF#1801  -  []  184.47 206.29 90 top
NOREF#1802  -  []  384.59 162.94 90 top
NOREF#1803  -  []  334.29 205.56 90 top
NOREF#1804  -  []  328.33 187.93 0 top
NOREF#1805  -  []  240.94 151.63 90 top
NOREF#1806  -  []  268.94 272.1 0 top
NOREF#1807  -  []  118.45 234.24 90 top
NOREF#1808  -  []  331.62 265.56 0 top
NOREF#1809  -  []  305.83 264.31 0 top
NOREF#1810  -  []  165.8 171.96 0 top
NOREF#1811  -  []  261.16 135.74 90 top
NOREF#1812  -  []  468.85 257.36 90 top
NOREF#1813  -  []  201.49 146.18 90 top
NOREF#1814  -  []  461.96 166.93 0 top
NOREF#1815  -  []  465.31 230.2 0 top
NOREF#1816  -  []  461.86 225.6 90 top
NOREF#1817  -  []  272.25 184.86 90 top
NOREF#1818  -  []  339.33 205.56 90 top
NOREF#1819  -  []  372.72 161.49 0 top
NOREF#1820  -  []  309.05 271.67 0 top
NOREF#1821  -  []  300.36 188.49 0 top
NOREF#1822  -  []  276.4 147.38 0 top
NOREF#1823  -  []  209.23 205.19 90 top
NOREF#1824  -  []  201.23 186.57 90 top
NOREF#1825  -  []  399.07 208.91 90 top
NOREF#1826  -  []  271.04 185.5 0 top
NOREF#1827  -  []  106.11 234.24 0 top
NOREF#1828  -  []  288.14 286.96 0 top
NOREF#1829  -  []  226.44 294.64 90 top
NOREF#1830  -  []  331.05 264.65 90 top
NOREF#1831  -  []  351.34 249.5 0 top
NOREF#1832  -  []  259.33 205.55 0 top
NOREF#1833  -  []  392.04 289.12 90 top
NOREF#1834  -  []  403.99 171.64 0 top
NOREF#1835  -  []  249.85 164.72 0 top
NOREF#1836  -  []  295.96 248.49 0 top
NOREF#1837  -  []  304.65 211.67 0 top
NOREF#1838  -  []  399.67 139.89 0 top
NOREF#1839  -  []  167.7 145.93 90 top
NOREF#1840  -  []  333.4 205.56 0 top
NOREF#1841  -  []  372.72 178.25 0 top
NOREF#1842  -  []  219.76 297.18 0 top
NOREF#1843  -  []  118.33 271.33 90 top
NOREF#1844  -  []  259.97 264.35 90 top
NOREF#1845  -  []  352.25 189.82 0 top
NOREF#1846  -  []  352.25 189.18 90 top
NOREF#1847  -  []  115.19 128.27 0 top
NOREF#1848  -  []  184.47 214 90 top
NOREF#1849  -  []  412.37 265.37 0 top
NOREF#1850  -  []  226.83 209.63 90 top
NOREF#1851  -  []  310.43 253.37 90 top
NOREF#1852  -  []  322.62 139.64 0 top
NOREF#1853  -  []  392.66 192.88 90 top
NOREF#1854  -  []  271.04 182.96 0 top
NOREF#1855  -  []  247.89 204.35 90 top
NOREF#1856  -  []  403.99 180.15 0 top
NOREF#1857  -  []  336.45 164.72 0 top
NOREF#1858  -  []  254.61 205.86 90 top
NOREF#1859  -  []  390.94 257.16 90 top
NOREF#1860  -  []  272.55 241.37 0 top
NOREF#1861  -  []  209.59 174.36 90 top
NOREF#1862  -  []  377.23 273.11 0 top
NOREF#1863  -  []  274.37 147.93 90 top
NOREF#1864  -  []  478.57 277.31 90 top
NOREF#1865  -  []  271.04 241.69 0 top
NOREF#1866  -  []  319.33 176.03 0 top
NOREF#1867  -  []  167.7 227.72 0 top
NOREF#1868  -  []  229.51 187.93 0 top
NOREF#1869  -  []  376.98 257.11 0 top
NOREF#1870  -  []  475.04 239.09 0 top
NOREF#1871  -  []  75.98 273.87 90 top
NOREF#1872  -  []  331.06 225.04 90 top
NOREF#1873  -  []  229.21 187.61 0 top
NOREF#1874  -  []  385.93 161.74 0 top
NOREF#1875  -  []  101.82 271.33 90 top
NOREF#1876  -  []  385.19 273.11 0 top
NOREF#1877  -  []  463.61 214.96 0 top
NOREF#1878  -  []  258.61 131.69 90 top
NOREF#1879  -  []  124.64 171.1 0 top
NOREF#1880  -  []  201.23 214 0 top
NOREF#1881  -  []  201.23 233.47 90 top
NOREF#1882  -  []  339.65 204.65 90 top
NOREF#1883  -  []  304.65 271.67 0 top
NOREF#1884  -  []  124.35 187.53 0 top
NOREF#1885  -  []  167.7 231.27 90 top
NOREF#1886  -  []  451.68 239.34 0 top
NOREF#1887  -  []  168.13 199.99 90 top
NOREF#1888  -  []  122.19 247.3 90 top
NOREF#1889  -  []  329.28 163.82 90 top
NOREF#1890  -  []  326.17 131.69 90 top
NOREF#1891  -  []  310.43 187.61 0 top
NOREF#1892  -  []  230.73 243.41 0 top
NOREF#1893  -  []  250.17 165.04 90 top
NOREF#1894  -  []  326.43 288.31 90 top
NOREF#1895  -  []  220.36 237.06 0 top
NOREF#1896  -  []  251.05 204.65 90 top
NOREF#1897  -  []  313.77 146.05 90 top
NOREF#1898  -  []  471.11 186.77 0 top
NOREF#1899  -  []  449.99 217.9 0 top
NOREF#1900  -  []  339.65 204.65 90 top
NOREF#1901  -  []  467.51 230.2 0 top
NOREF#1902  -  []  448.94 292.92 90 top
NOREF#1903  -  []  271.34 185.18 0 top
NOREF#1904  -  []  182.82 230.19 90 top
NOREF#1905  -  []  453.84 179.06 0 top
NOREF#1906  -  []  230.43 253.37 90 top
NOREF#1907  -  []  106.76 222.88 0 top
NOREF#1908  -  []  266.49 143.19 0 top
NOREF#1909  -  []  482.64 235.89 90 top
NOREF#1910  -  []  249.15 296.86 0 top
NOREF#1911  -  []  297.71 276.09 0 top
NOREF#1912  -  []  167.7 247.18 90 top
NOREF#1913  -  []  417.87 257.37 0 top
NOREF#1914  -  []  234.33 168.13 90 top
NOREF#1915  -  []  373.93 281.11 0 top
NOREF#1916  -  []  271.34 249.5 0 top
NOREF#1917  -  []  381.2 274.38 90 top
NOREF#1918  -  []  451.64 222.5 0 top
NOREF#1919  -  []  201.23 227.72 90 top
NOREF#1920  -  []  118.33 286.94 90 top
NOREF#1921  -  []  316.43 132.91 90 top
NOREF#1922  -  []  209.23 222.95 90 top
NOREF#1923  -  []  461.96 210.36 0 top
NOREF#1924  -  []  215.96 237.06 0 top
NOREF#1925  -  []  184.47 256.5 90 top
NOREF#1926  -  []  201.23 206.29 90 top
NOREF#1927  -  []  408.63 274.64 90 top
NOREF#1928  -  []  420.88 129.99 90 top
NOREF#1929  -  []  511.59 293.82 90 top
NOREF#1930  -  []  285.71 280.1 0 top
NOREF#1931  -  []  259.88 288.41 90 top
NOREF#1932  -  []  116.27 171.02 0 top
NOREF#1933  -  []  201.49 147.53 90 top
NOREF#1934  -  []  381.74 297.12 0 top
NOREF#1935  -  []  166.06 257.62 90 top
NOREF#1936  -  []  168.69 276.04 90 top
NOREF#1937  -  []  261.82 290.13 90 top
NOREF#1938  -  []  209.33 201.79 90 top
NOREF#1939  -  []  501.87 273.87 90 top
NOREF#1940  -  []  385.19 265.11 0 top
NOREF#1941  -  []  230.43 194.01 0 top
NOREF#1942  -  []  127.95 187.53 0 top
NOREF#1943  -  []  167.7 206.29 90 top
NOREF#1944  -  []  192.47 216.45 90 top
NOREF#1945  -  []  128.05 271.33 90 top
NOREF#1946  -  []  306.83 209.63 90 top
NOREF#1947  -  []  479.44 239.09 0 top
NOREF#1948  -  []  283.21 270.2 90 top
NOREF#1949  -  []  194.09 187.32 90 top
NOREF#1950  -  []  343.31 224.72 0 top
NOREF#1951  -  []  377.32 180.15 0 top
NOREF#1952  -  []  175.7 202.99 90 top
NOREF#1953  -  []  222.11 252.14 0 top
NOREF#1954  -  []  379.01 272.66 90 top
NOREF#1955  -  []  277.5 155.38 0 top
NOREF#1956  -  []  118.45 239.39 0 top
NOREF#1957  -  []  405.93 288.57 90 top
NOREF#1958  -  []  263.2 232.26 90 top
NOREF#1959  -  []  115.36 235.64 0 top
NOREF#1960  -  []  259.97 204.35 90 top
NOREF#1961  -  []  118.99 171.65 0 top
NOREF#1962  -  []  418.37 289.17 90 top
NOREF#1963  -  []  209.49 177.76 90 top
NOREF#1964  -  []  175.8 187.82 90 top
NOREF#1965  -  []  352.24 244.86 90 top
NOREF#1966  -  []  237.2 296.61 0 top
NOREF#1967  -  []  408.02 239.21 0 top
NOREF#1968  -  []  165.8 254 90 top
NOREF#1969  -  []  378.58 289.12 90 top
NOREF#1970  -  []  118.96 174.04 90 top
NOREF#1971  -  []  400.85 281.11 0 top
NOREF#1972  -  []  124.35 222.33 0 top
NOREF#1973  -  []  351.04 189.82 0 top
NOREF#1974  -  []  398.53 178.25 90 top
NOREF#1975  -  []  172.08 291.65 90 top
NOREF#1976  -  []  199.59 171.96 0 top
NOREF#1977  -  []  93.76 287.84 90 top
NOREF#1978  -  []  406.44 154.88 0 top
NOREF#1979  -  []  395.2 281.11 0 top
NOREF#1980  -  []  326 288.86 90 top
NOREF#1981  -  []  209.23 243.88 90 top
NOREF#1982  -  []  262.09 143.19 0 top
NOREF#1983  -  []  337.09 224.74 90 top
NOREF#1984  -  []  333.72 264.65 90 top
NOREF#1985  -  []  385.19 297.12 0 top
NOREF#1986  -  []  388.43 146.88 0 top
NOREF#1987  -  []  263.95 224.74 90 top
NOREF#1988  -  []  107.02 171.57 0 top
NOREF#1989  -  []  392.04 257.11 90 top
NOREF#1990  -  []  310.73 189.2 0 top
NOREF#1991  -  []  111.54 287.84 90 top
NOREF#1992  -  []  218.16 177.06 0 top
NOREF#1993  -  []  271.04 249.82 0 top
NOREF#1994  -  []  118.99 171.65 0 top
NOREF#1995  -  []  398.65 233.11 0 top
NOREF#1996  -  []  352.55 242.64 0 top
NOREF#1997  -  []  477.24 195.66 0 top
NOREF#1998  -  []  106.36 190.55 0 top
NOREF#1999  -  []  353.35 288.41 90 top
NOREF#2000  -  []  333.33 181.33 90 top
NOREF#2001  -  []  167.7 134.07 90 top
NOREF#2002  -  []  122.44 171.1 0 top
NOREF#2003  -  []  343.95 163.52 90 top
NOREF#2004  -  []  377.32 171.39 0 top
NOREF#2005  -  []  310.43 187.61 90 top
NOREF#2006  -  []  100.98 195.15 0 top
NOREF#2007  -  []  334.29 265.56 0 top
NOREF#2008  -  []  465.45 292.92 90 top
NOREF#2009  -  []  398.65 241.11 0 top
NOREF#2010  -  []  251.94 265.86 90 top
NOREF#2011  -  []  306.27 156.63 90 top
NOREF#2012  -  []  184.89 159.1 90 top
NOREF#2013  -  []  201.49 159.65 0 top
NOREF#2014  -  []  394.05 287.22 0 top
NOREF#2015  -  []  201.91 172.56 90 top
NOREF#2016  -  []  260.6 286.96 90 top
NOREF#2017  -  []  352.24 249.18 90 top
NOREF#2018  -  []  230.43 249.52 0 top
NOREF#2019  -  []  250.74 224.74 0 top
NOREF#2020  -  []  339.65 205.86 90 top
NOREF#2021  -  []  390.69 224.85 0 top
NOREF#2022  -  []  184.47 178.86 90 top
NOREF#2023  -  []  398.65 297.12 0 top
NOREF#2024  -  []  263.31 224.72 0 top
NOREF#2025  -  []  415.1 163.64 0 top
NOREF#2026  -  []  353.35 288.31 90 top
NOREF#2027  -  []  385.19 224.85 0 top
NOREF#2028  -  []  367.73 274.38 90 top
NOREF#2029  -  []  319.15 288.86 0 top
NOREF#2030  -  []  230.43 188.88 90 top
NOREF#2031  -  []  94.93 190.55 0 top
NOREF#2032  -  []  229.05 271.67 0 top
NOREF#2033  -  []  342.68 224.74 90 top
NOREF#2034  -  []  224.65 271.67 0 top
NOREF#2035  -  []  230.73 246.66 0 top
NOREF#2036  -  []  175.7 250.38 90 top
NOREF#2037  -  []  290.11 280.1 0 top
NOREF#2038  -  []  265.39 135.19 0 top
NOREF#2039  -  []  241.82 227.13 90 top
NOREF#2040  -  []  334.29 265.56 90 top
NOREF#2041  -  []  412.37 257.37 0 top
NOREF#2042  -  []  418.37 241.16 90 top
NOREF#2043  -  []  249.28 165.04 90 top
NOREF#2044  -  []  184.89 145.38 90 top
NOREF#2045  -  []  378.58 273.11 90 top
NOREF#2046  -  []  461.96 210.36 0 top
NOREF#2047  -  []  254.29 204.35 90 top
NOREF#2048  -  []  352.25 249.18 90 top
NOREF#2049  -  []  167.7 163.2 90 top
NOREF#2050  -  []  303.56 185.29 90 top
NOREF#2051  -  []  387.08 171.64 0 top
NOREF#2052  -  []  327.25 205.55 0 top
NOREF#2053  -  []  386.46 139.89 0 top
NOREF#2054  -  []  410.52 273.37 0 top
NOREF#2055  -  []  263.31 224.74 0 top
NOREF#2056  -  []  413.71 178.82 90 top
NOREF#2057  -  []  400.25 148.15 90 top
NOREF#2058  -  []  327.89 264.35 90 top
NOREF#2059  -  []  184.47 159.65 90 top
NOREF#2060  -  []  383.09 273.11 0 top
NOREF#2061  -  []  371.48 249.11 0 top
NOREF#2062  -  []  271.56 288.91 90 top
NOREF#2063  -  []  230.43 247.61 90 top
NOREF#2064  -  []  175.7 218.65 90 top
NOREF#2065  -  []  402.14 146.88 0 top
NOREF#2066  -  []  201.23 231.27 90 top
NOREF#2067  -  []  184.47 258.7 90 top
NOREF#2068  -  []  459.28 236.14 90 top
NOREF#2069  -  []  168.69 292.55 90 top
NOREF#2070  -  []  127.55 219.13 90 top
NOREF#2071  -  []  396.03 163.64 0 top
NOREF#2072  -  []  388.43 163.64 0 top
NOREF#2073  -  []  167.7 165.4 90 top
NOREF#2074  -  []  127.3 228.02 90 top
NOREF#2075  -  []  262.68 164.74 90 top
NOREF#2076  -  []  262.04 164.72 0 top
NOREF#2077  -  []  404.4 273.16 90 top
NOREF#2078  -  []  332.51 205.56 90 top
NOREF#2079  -  []  217.71 276.09 0 top
NOREF#2080  -  []  313.98 131.09 90 top
NOREF#2081  -  []  303.84 288.86 0 top
NOREF#2082  -  []  333.33 241.33 90 top
NOREF#2083  -  []  230.43 193.37 90 top
NOREF#2084  -  []  298.16 188.49 0 top
NOREF#2085  -  []  257.09 164.74 90 top
NOREF#2086  -  []  250.49 164.74 90 top
NOREF#2087  -  []  351.83 288.91 90 top
NOREF#2088  -  []  286.81 272.1 0 top
NOREF#2089  -  []  108.27 171.02 0 top
NOREF#2090  -  []  229.51 249.2 0 top
NOREF#2091  -  []  298.13 214.06 90 top
NOREF#2092  -  []  253.4 205.55 0 top
NOREF#2093  -  []  237.83 197.63 0 top
NOREF#2094  -  []  471.21 175.95 0 top
NOREF#2095  -  []  250.17 163.82 90 top
NOREF#2096  -  []  252.83 205.86 90 top
NOREF#2097  -  []  230.43 247.61 0 top
NOREF#2098  -  []  192.47 230.17 90 top
NOREF#2099  -  []  127.59 211.59 90 top
NOREF#2100  -  []  330.74 164.74 0 top
NOREF#2101  -  []  289.29 296.86 0 top
NOREF#2102  -  []  167.7 176.66 90 top
NOREF#2103  -  []  456.08 239.34 0 top
NOREF#2104  -  []  299.81 213.69 90 top
NOREF#2105  -  []  168.13 132.17 90 top
NOREF#2106  -  []  407.77 255.47 0 top
NOREF#2107  -  []  98.78 195.15 0 top
NOREF#2108  -  []  273.24 272.1 0 top
NOREF#2109  -  []  96.33 238.84 0 top
NOREF#2110  -  []  379.48 239.21 90 top
NOREF#2111  -  []  450.03 166.93 0 top
NOREF#2112  -  []  286.55 288.31 90 top
NOREF#2113  -  []  373.68 249.11 0 top
NOREF#2114  -  []  329.85 164.72 0 top
NOREF#2115  -  []  127.84 167.9 90 top
NOREF#2116  -  []  309.21 243.09 0 top
NOREF#2117  -  []  238.3 288.61 0 top
NOREF#2118  -  []  259.33 204.35 90 top
NOREF#2119  -  []  226.85 271.67 0 top
NOREF#2120  -  []  182.57 185.42 90 top
NOREF#2121  -  []  375.22 163.39 0 top
NOREF#2122  -  []  380.59 255.21 0 top
NOREF#2123  -  []  248.96 164.72 0 top
NOREF#2124  -  []  352.55 189.5 0 top
NOREF#2125  -  []  376.98 241.11 0 top
NOREF#2126  -  []  199.33 226.57 0 top
NOREF#2127  -  []  222.67 298 90 top
NOREF#2128  -  []  343.95 223.52 90 top
NOREF#2129  -  []  383.09 289.12 0 top
NOREF#2130  -  []  184.47 217.55 90 top
NOREF#2131  -  []  377.23 241.16 90 top
NOREF#2132  -  []  450.03 191.31 0 top
NOREF#2133  -  []  419.9 154.88 0 top
NOREF#2134  -  []  369.38 224.6 0 top
NOREF#2135  -  []  177.33 242.18 90 top
NOREF#2136  -  []  297.41 213.24 90 top
NOREF#2137  -  []  209.49 155.13 90 top
NOREF#2138  -  []  94.93 190.55 0 top
NOREF#2139  -  []  199.33 199.39 0 top
NOREF#2140  -  []  210.86 242.18 90 top
NOREF#2141  -  []  351.58 288.86 0 top
NOREF#2142  -  []  378.75 256.66 90 top
NOREF#2143  -  []  405.93 288.67 90 top
